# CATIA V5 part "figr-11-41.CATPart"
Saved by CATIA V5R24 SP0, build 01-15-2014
Part number: Part1
Bounding box of the stored display mesh (mm): x -59 to 59, y -60 to 60, z 0 to 39.8
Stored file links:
  D:\KAVITA\CATIA V5-6R2014 Project_ Kavita\CATIA V5-6R2014_partfiles\Partfiles\c11_catia_v5-6r2014_prt\figr-11-41.CATPart
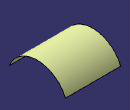
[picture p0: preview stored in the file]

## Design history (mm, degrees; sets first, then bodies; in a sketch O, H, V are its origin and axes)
Set1
  Extrude1: Element1 Sketch1, Lim1 59, Lim2 59, Direction yz-plane
Body1 (main body)
  Sketch1 on yz-plane, origin (0, 0, 0), H (0, 1, 0), V (0, 0, 1)
    arc A1 centre (0, -25) radius 65 from (-60, 0) to (60, 0) cw
    point P2 (-60, 0)
    point P3 (60, 0)
    coincidence: P2 H, P3 H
